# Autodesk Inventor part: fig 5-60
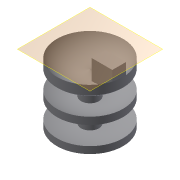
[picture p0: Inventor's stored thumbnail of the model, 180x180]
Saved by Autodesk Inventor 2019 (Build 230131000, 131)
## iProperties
Created: 2004-05
Part Number: fig 5-60
Document SubType Name: Modeling
Designer: CADCIM Technologies
Manufacturer: Standard
Standards Organization: Custom
Density: 1 g/cm^3
Material: Generic
Appearance: Default
Author: CADCIM Technologies
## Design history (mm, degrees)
sketch "Sketch1"
  geometry: L1 (0.098, 22.743)-(0.098, 0.516); L2 (-3.621, 19.305)-(-3.621, 13.061); L3 (-3.621, 10.379)-(-3.621, 3.25); L4 (-3.664, 0.516)-(0.098, 0.516); L5 (-13.694, 4.7)-(-13.694, 1.836); L6 (-13.694, 26.851)-(-13.694, 23.014); L7 (-13.694, 15.335)-(-13.694, 12.343); A1 r 10.546 centre (-4.597, 32.185) between (-13.694, 26.851) and (0.098, 22.743); A2 r 21.828 centre (-4.597, 32.185) between (-13.694, 12.343) and (-3.621, 10.379); A3 r 12.918 centre (-4.597, 32.185) between (-13.694, 23.014) and (-3.621, 19.305); A4 r 19.149 centre (-4.597, 32.185) between (-13.694, 15.335) and (-3.621, 13.061); A5 r 28.952 centre (-4.597, 32.185) between (-13.694, 4.7) and (-3.621, 3.25); A6 r 31.683 centre (-4.597, 32.185) between (-13.694, 1.836) and (-3.664, 0.516)
  constraints: 14 end point, 12 point on circle, 6 centre point, 4 perpendicular, 2 parallel, 1 vertical
revolve "Revolution1" sketch "Sketch1" stored, may be unused: angle "d0" = 90 deg
workplane "Work Plane1"
sketch "Sketch2"
  geometry: L1 (3.408, -2.846)-(12.06, -2.846); L2 (12.06, -2.846)-(12.06, 2.873); L3 (12.06, 2.873)-(3.408, 2.873); L4 (3.408, 2.873)-(3.408, -2.846)
  constraints: 8 end point, 2 parallel, 1 horizontal, 1 perpendicular
extrude "Extrusion3" join sketch "Sketch2" stored distance "d8" = 10; taper "d9" = 0 deg
body "Solid1"
